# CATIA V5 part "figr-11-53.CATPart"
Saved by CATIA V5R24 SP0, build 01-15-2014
Part number: Part1
Bounding box of the stored display mesh (mm): x -70 to 82, y -90 to 90, z 0 to 80.806
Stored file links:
  D:\KAVITA\CATIA V5-6R2014 Project_ Kavita\CATIA V5-6R2014_partfiles\Partfiles\c11_catia_v5-6r2014_prt\figr-11-53.CATPart
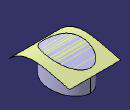
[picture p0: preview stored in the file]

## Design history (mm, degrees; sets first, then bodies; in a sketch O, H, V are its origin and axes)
Set1
  Extrude1: Element1 Sketch2, Lim1 82, Lim2 70, Direction yz-plane
Body1 (main body)
  Sketch1 on xy-plane, origin (0, 0, 0), H (1, 0, 0), V (0, 1, 0)
    ellipse A1 centre (0, 0) semi-axes 70, 50 rotation 90
    point P1 (50, 0)
    coincidence: P1 H, A1 P1
  Pad1: profile Sketch1, direction (0, 0, 1), length 84
  Split1: SplitPlane Extrude1
  Sketch2 on yz-plane, origin (0, 0, 0), H (0, 1, 0), V (0, 0, 1)
    spline S1 through (-90, 50) (-30, 80) (50, 70) (90, 60)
